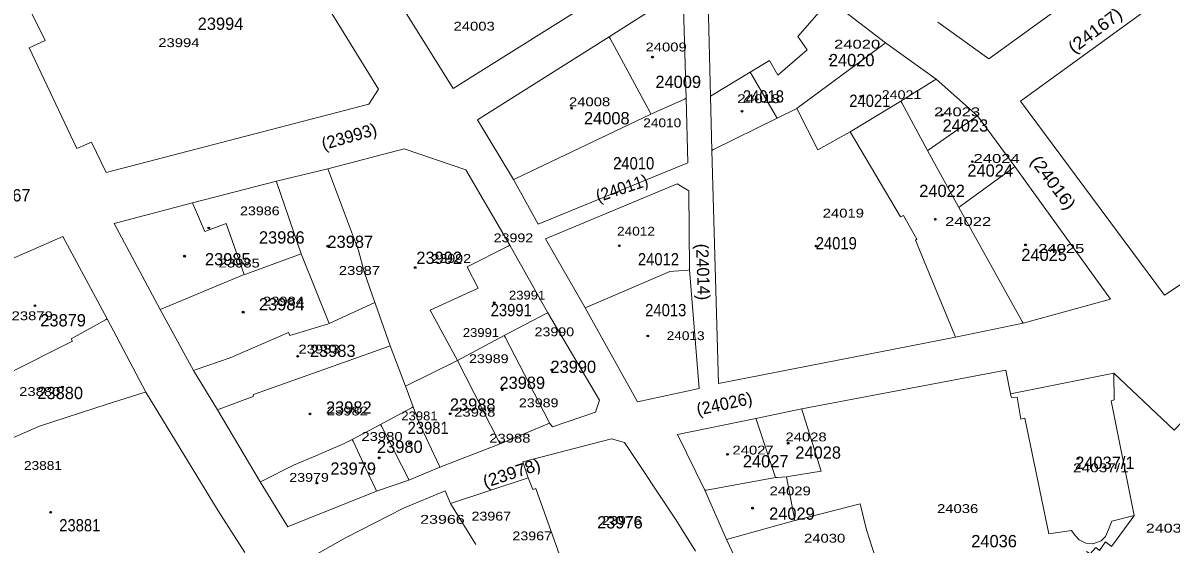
# Model space of a CAD drawing. Extents: x 649608 to 651081, y 237980 to 241202.
# Drawn here: x 650489.8 to 650826.5, y 238507.5 to 238660.5 of the extents above; entities that cross this region are included whole.
import ezdxf

# ---------------------------------------------------------------- set-up
doc = ezdxf.new("R2010")
doc.units = 0
doc.header["$PDMODE"] = 32
doc.header["$PDSIZE"] = 0.5
for name, color, linetype in [('19', 7, 'Continuous'), ('20', 7, 'Continuous'), ('6', 7, 'Continuous')]:
    doc.layers.add(name, color=color, linetype=linetype)
doc.layers.add('3', color=7, linetype='Continuous', lineweight=13)
doc.layers.add('5', color=7, linetype='Continuous', lineweight=13)

msp = doc.modelspace()

# ---------------------------------------------------------------- linework, layer by layer
at = {"layer": '3'}
for p, q in [((650640.911, 238601.421), (650633.733, 238614.499)), ((650685.081, 238611.156), (650685.298, 238587.976))]:
    msp.add_line(p, q, dxfattribs=at)
msp.add_lwpolyline([(650594.152, 238641.02), (650591.238, 238636.62), (650514.199, 238616.533), (650509.905, 238625.434), (650505.659, 238623.615), (650491.621, 238653.156), (650496.299, 238655.283), (650492.007, 238664.059), (650546.626, 238718.198)], close=True, dxfattribs=at)
for points in [[(650851.505, 238687.244), (650818.255, 238663.558), (650782.391, 238637.529), (650824.601, 238580.584), (650833.018, 238586.179), (650832.688, 238586.745), (650893.931, 238625.308)], [(650691.506, 238638.961), (650690.613, 238674.266), (650704.689, 238683.423), (650726.518, 238667.275), (650742.789, 238654.588), (650757.655, 238644.002), (650769.738, 238633.206), (650780.745, 238618.283), (650808.842, 238579.434)], [(650821.773, 238685.221), (650773.098, 238649.879), (650758.169, 238660.693)], [(650652.377, 238664), (650615.997, 238641.193), (650602.016, 238663.671), (650591.619, 238681.099)], [(650661.791, 238656.398), (650678.716, 238667.17), (650683.54, 238664.897), (650684.332, 238638.366), (650684.833, 238619.402)], [(650633.733, 238614.499), (650623.098, 238632.061), (650661.791, 238656.398)], [(650763.334, 238568.243), (650693.809, 238554.607), (650691.843, 238623.047), (650691.506, 238638.961)], [(650632.652, 238595.212), (650619.696, 238617.401), (650601.662, 238623.481), (650579.269, 238617.651), (650564.158, 238614.006), (650539.521, 238607.693)], [(650640.911, 238601.421), (650646.456, 238603.634), (650684.833, 238619.402)], [(650643.082, 238597.059), (650681.735, 238613.259), (650685.081, 238611.156)], [(650539.521, 238607.693), (650516.543, 238601.628), (650530.097, 238576.345), (650539.885, 238558.481), (650546.918, 238546.889), (650559.402, 238525.78)], [(650514.565, 238573.659), (650501.562, 238597.783), (650470.671, 238584.303), (650457.326, 238578.233), (650445.045, 238572.958), (650428.006, 238565.908), (650411.173, 238558.735)], [(650685.298, 238587.976), (650688.11, 238553.211), (650670.09, 238549.229), (650654.686, 238576.871), (650643.082, 238597.059)], [(650644.294, 238542.988), (650645.176, 238541.889), (650657.723, 238546.209), (650658.934, 238549.806), (650643.817, 238575.424), (650632.652, 238595.212)], [(650808.842, 238579.434), (650783.192, 238572.377), (650763.334, 238568.243)], [(650554.863, 238505.063), (650547.107, 238517.326), (650525.879, 238552.125), (650514.565, 238573.659)], [(650779.446, 238551.594), (650778.139, 238558.54), (650718.246, 238547.194), (650704.787, 238544.402)], [(650856.496, 238513.231), (650844.324, 238525.087), (650848.714, 238529.96), (650832.101, 238545.72), (650827.429, 238540.969), (650809.783, 238557.7), (650779.446, 238551.594)], [(650567.52, 238512.624), (650567.925, 238512.787), (650593.521, 238523.054), (650603.014, 238526.326), (650612.093, 238530.073), (650629.748, 238536.928), (650644.294, 238542.988)], [(650704.787, 238544.402), (650681.818, 238539.725), (650689.852, 238523.302), (650696.151, 238508.876)], [(650687.044, 238505.407), (650681.393, 238514.544), (650666.233, 238537.335), (650662.489, 238538.449), (650636.452, 238531.69), (650637.963, 238526.941), (650615.232, 238519.416)], [(650559.402, 238525.78), (650567.235, 238513.086), (650567.52, 238512.624)], [(650615.232, 238519.416), (650613.655, 238523.18), (650601.449, 238518.058), (650584.454, 238509.394), (650573.208, 238503.022)], [(650770.127, 238405.165), (650755.807, 238391.194), (650744.776, 238410.239), (650745.518, 238410.844), (650732.624, 238431.532), (650720.683, 238456.081), (650711.443, 238476.563), (650696.151, 238508.876)]]:
    msp.add_lwpolyline(points, dxfattribs=at)
at = {"layer": '5'}
for points in [[(650717.112, 238656.511), (650726.081, 238666.775), (650726.518, 238667.275)], [(650661.791, 238656.398), (650662.06, 238655.898), (650673.743, 238634.196), (650674.012, 238633.696)], [(650703.102, 238646.043), (650708.761, 238649.394), (650711.238, 238645.161), (650719.841, 238652.534), (650717.112, 238656.511)], [(650716.794, 238635.342), (650717.294, 238635.712), (650742.289, 238654.218), (650742.789, 238654.588)], [(650691.506, 238638.961), (650692.006, 238639.266), (650703.102, 238646.043)], [(650703.102, 238646.043), (650703.395, 238645.543), (650710.759, 238632.97), (650711.052, 238632.47)], [(650747.305, 238637.49), (650757.155, 238643.687), (650757.655, 238644.002)], [(650674.012, 238633.696), (650683.832, 238638.14), (650684.332, 238638.366)], [(650732.46, 238628.526), (650732.96, 238628.828), (650747.305, 238637.49)], [(650755.113, 238622.982), (650747.574, 238636.99), (650747.305, 238637.49)], [(650633.733, 238614.499), (650634.233, 238614.737), (650674.012, 238633.696)], [(650691.843, 238623.047), (650692.343, 238623.292), (650711.052, 238632.47), (650716.794, 238635.342)], [(650716.794, 238635.342), (650722.99, 238623.236), (650732.46, 238628.526)], [(650755.113, 238622.982), (650755.613, 238623.332), (650769.238, 238632.856), (650769.738, 238633.206)], [(650732.46, 238628.526), (650747.225, 238603.532), (650748.041, 238603.925), (650752.04, 238596.986), (650751.632, 238596.701), (650763.128, 238568.743), (650763.334, 238568.243)], [(650783.192, 238572.377), (650782.914, 238572.877), (650764.3, 238606.322), (650755.113, 238622.982)], [(650579.269, 238617.651), (650579.457, 238617.151), (650588.284, 238593.698), (650589.864, 238587.462), (650593.06, 238578.42), (650579.665, 238572.248)], [(650764.3, 238606.322), (650764.8, 238606.686), (650780.245, 238617.919), (650780.745, 238618.283)], [(650571.406, 238592.679), (650564.328, 238613.506), (650564.158, 238614.006)], [(650539.521, 238607.693), (650539.738, 238607.193), (650543.17, 238599.288), (650549.456, 238601.561), (650554.662, 238586.592)], [(650554.662, 238586.592), (650555.162, 238586.774), (650571.406, 238592.679)], [(650579.665, 238572.248), (650571.608, 238592.179), (650571.406, 238592.679)], [(650632.652, 238595.212), (650632.152, 238594.959), (650620.128, 238588.875), (650623.291, 238582.659), (650609.236, 238576.176), (650617.25, 238561.443), (650630.991, 238568.704)], [(650554.662, 238586.592), (650530.597, 238576.554), (650530.097, 238576.345)], [(650654.686, 238576.871), (650655.186, 238577.085), (650679.554, 238587.526), (650684.798, 238587.937), (650685.298, 238587.976)], [(650597.5, 238565.686), (650593.234, 238577.92), (650593.06, 238578.42)], [(650630.991, 238568.704), (650643.317, 238575.162), (650643.817, 238575.424)], [(650484.63, 238557.158), (650485.13, 238557.408), (650504.385, 238567.04), (650503.968, 238567.761), (650514.065, 238573.381), (650514.565, 238573.659)], [(650579.665, 238572.248), (650579.165, 238572.097), (650568.13, 238568.774), (650567.737, 238569.576), (650550.626, 238562.147), (650540.385, 238558.652), (650539.885, 238558.481)], [(650630.991, 238568.704), (650631.25, 238568.204), (650644.035, 238543.488), (650644.294, 238542.988)], [(650597.5, 238565.686), (650597, 238565.508), (650557.445, 238551.411), (650557.349, 238550.854), (650547.418, 238547.079), (650546.918, 238546.889)], [(650617.25, 238561.443), (650602.006, 238553.886), (650597.5, 238565.686)], [(650617.25, 238561.443), (650629.493, 238537.428), (650629.748, 238536.928)], [(650815.76, 238515.874), (650808.982, 238549.567), (650809.848, 238549.856), (650809.787, 238557.2), (650809.783, 238557.7)], [(650525.879, 238552.125), (650525.379, 238551.97), (650514.498, 238548.602), (650494.718, 238542.098), (650474.912, 238533.525), (650466.099, 238547.239), (650465.778, 238547.739)], [(650602.006, 238553.886), (650602.19, 238553.386), (650604.249, 238547.784)], [(650790.754, 238510.566), (650783.667, 238544.482), (650782.521, 238544.14), (650781.398, 238550.685), (650779.79, 238550.513), (650779.605, 238551.094), (650779.446, 238551.594)], [(650604.249, 238547.784), (650603.749, 238547.514), (650594.7, 238542.619), (650586.421, 238538.202)], [(650604.249, 238547.784), (650605.882, 238543.541), (650611.862, 238530.573), (650612.093, 238530.073)], [(650713.724, 238527.259), (650714.224, 238527.342), (650723.9, 238528.951), (650718.401, 238546.694), (650718.246, 238547.194)], [(650594.7, 238542.619), (650594.955, 238542.119), (650602.759, 238526.826), (650603.014, 238526.326)], [(650710.532, 238527.068), (650704.953, 238543.902), (650704.787, 238544.402)], [(650586.421, 238538.202), (650584.033, 238537.012), (650575.693, 238533.426), (650569.132, 238530.67), (650559.902, 238526.031), (650559.402, 238525.78)], [(650586.421, 238538.202), (650586.655, 238537.702), (650590.403, 238529.7), (650593.286, 238523.554), (650593.521, 238523.054)], [(650637.963, 238526.941), (650638.166, 238526.441), (650639.331, 238523.578), (650640.223, 238523.816), (650647.193, 238504.378), (650646.46, 238503.894), (650647.011, 238502.484)], [(650689.852, 238523.302), (650690.352, 238523.393), (650710.532, 238527.068)], [(650696.151, 238508.876), (650716.197, 238514.45), (650713.724, 238527.259)], [(650713.724, 238527.259), (650711.032, 238527.098), (650710.532, 238527.068)], [(650615.232, 238519.416), (650615.543, 238518.916), (650622.678, 238507.426)], [(650716.197, 238514.45), (650716.697, 238514.578), (650735.331, 238519.332), (650737.208, 238511.711), (650740.707, 238500.782), (650741.379, 238500.793), (650745.427, 238492.156)], [(650790.754, 238510.566), (650797.335, 238511.557), (650798.4, 238510.056), (650799.565, 238508.759), (650801.595, 238507.776), (650803.641, 238507.599), (650806.008, 238508.436), (650807.322, 238509.739), (650808.243, 238511.819), (650809.187, 238514.203), (650815.76, 238515.874)], [(650815.76, 238515.874), (650815.392, 238515.374), (650809.118, 238506.861), (650807.289, 238508.15), (650805.53, 238505.605), (650804.445, 238506.55), (650802.807, 238504.638), (650801.776, 238505.381)]]:
    msp.add_lwpolyline(points, dxfattribs=at)
at = {"layer": '6'}
for p in [(650674.487, 238650.433), (650726.577, 238649.872), (650735.591, 238638.912), (650650.776, 238635.448), (650700.718, 238634.545), (650759.437, 238633.492), (650664.936, 238619.893), (650768.27, 238619.764), (650757.437, 238602.866), (650544.348, 238600.299), (650783.882, 238595.33), (650537.234, 238592.019), (650579.224, 238594.949), (650664.73, 238595.065), (650722.496, 238594.974), (650604.89, 238588.683), (650493.348, 238577.47), (650554.417, 238575.58), (650628.039, 238578.327), (650673.08, 238568.602), (650570.393, 238562.654), (650644.95, 238558.656), (650501.452, 238553.592), (650630.429, 238552.816), (650574.029, 238545.733), (650615.138, 238545.758), (650603.206, 238537.055), (650714.281, 238537.131), (650594.313, 238532.836), (650696.487, 238533.852), (650799.262, 238532.649), (650576.021, 238525.413), (650703.818, 238518.067), (650497.97, 238516.876), (650662.052, 238515.362)]:
    msp.add_point(p, dxfattribs=at)

# ---------------------------------------------------------------- texts
at = {"layer": '19'}
for s, rotation, width, p in [('(24167)', 37.028, 1.1, (650798.048, 238651.337)), ('(24016)', 306.845, 1.1, (650785.071, 238619.858)), ('(24011)', 18.398, 0.95, (650658.569, 238607.802)), ('(23978)', 18.317, 1.05, (650625.428, 238523.944))]:
    msp.add_text(s, height=3.6, rotation=rotation, dxfattribs=dict(at, width=width)).set_placement(p)
for s, p in [('23994', (650541.083, 238658.432)), ('24020', (650726.195, 238647.767)), ('24009', (650675.32, 238641.367)), ('24008', (650654.373, 238630.702)), ('24023', (650759.541, 238628.569)), ('24024', (650766.809, 238615.344)), ('24022', (650752.701, 238609.372)), ('23867', (650478.667, 238608.091)), ('23986', (650559.038, 238595.72)), ('23987', (650579.131, 238594.44)), ('23985', (650543.22, 238589.321)), ('23992', (650605.209, 238589.747)), ('24025', (650782.627, 238590.601)), ('23984', (650559.037, 238576.096)), ('23879', (650494.912, 238571.403)), ('23983', (650574.001, 238562.444)), ('23990', (650644.54, 238557.751)), ('23989', (650629.578, 238553.059)), ('23880', (650494.056, 238550.072)), ('23982', (650578.704, 238545.806)), ('23988', (650615.042, 238546.66)), ('23980', (650593.666, 238534.288)), ('24028', (650716.361, 238532.583)), ('24027', (650700.971, 238530.023)), ('24037/1', (650798.444, 238529.596)), ('23979', (650579.985, 238527.889)), ('24029', (650708.666, 238514.665)), ('23976', (650658.22, 238512.105)), ('24036', (650767.957, 238506.6))]:
    msp.add_text(s, height=3.6, dxfattribs=at).set_placement(p)
at = {"layer": '19', "width": 0.9}
for s, p in [('24018', (650700.971, 238637.101)), ('24021', (650732.18, 238635.821)), ('24010', (650662.923, 238617.477)), ('24019', (650722.347, 238594.014)), ('24012', (650670.19, 238589.321)), ('23991', (650627.013, 238574.389)), ('24013', (650672.328, 238574.389)), ('23981', (650602.644, 238539.834)), ('23881', (650500.47, 238511.251))]:
    msp.add_text(s, height=3.6, dxfattribs=at).set_placement(p)
at = {"layer": '19'}
for s, rotation, p in [('(23993)', 16.023, (650578.008, 238623.119)), ('(24014)', 271.851, (650687.241, 238595.628)), ('(24026)', 11.984, (650687.781, 238545.243))]:
    msp.add_text(s, height=3.6, rotation=rotation, dxfattribs=at).set_placement(p)
at = {"layer": '20'}
for s, width, p in [('24003', 1.25, (650616.117, 238658.202)), ('23994', 1.25, (650529.517, 238653.369)), ('24009', 1.25, (650672.414, 238652.098)), ('24020 ', 1.4, (650727.713, 238652.916)), ('24018 ', 1.3, (650699.277, 238636.927)), ('24021 ', 1.2, (650741.704, 238638.104)), ('24008', 1.25, (650649.975, 238636.018)), ('24023 ', 1.4, (650757.04, 238633.063)), ('24010', 1.15, (650671.767, 238629.848)), ('24024 ', 1.4, (650768.635, 238619.384)), ('23986', 1.2, (650553.499, 238604.019)), ('24019 ', 1.25, (650724.397, 238603.352)), ('24022 ', 1.4, (650760.278, 238600.913)), ('24012', 1.15, (650664.063, 238598.043)), ('23992', 1.2, (650627.875, 238596.104)), ('24025 ', 1.4, (650787.581, 238592.984)), ('23992', 1.2, (650609.654, 238590.048)), ('23985', 1.25, (650547.214, 238588.695)), ('23987', 1.25, (650582.465, 238586.52)), ('23984', 1.25, (650560.188, 238577.534)), ('23991', 1.1, (650632.373, 238579.277)), ('23879', 1.25, (650486.505, 238573.23)), ('23991', 1.1, (650618.839, 238568.292)), ('23990', 1.2, (650639.877, 238568.526)), ('24013', 1.15, (650678.631, 238567.379)), ('23983', 1.25, (650570.633, 238563.44)), ('23989', 1.2, (650620.653, 238560.63)), ('23880', 1.25, (650488.712, 238550.975)), ('23989', 1.2, (650635.286, 238547.678)), ('23982', 1.25, (650578.937, 238545.272)), ('23981', 1.1, (650600.798, 238543.853)), ('23988', 1.25, (650616.302, 238544.928)), ('23980', 1.25, (650589.095, 238537.799)), ('23988', 1.25, (650626.591, 238537.301)), ('24028', 1.25, (650713.461, 238537.67)), ('24027', 1.25, (650697.922, 238533.819)), ('23881', 1.15, (650490.138, 238529.294)), ('23979', 1.2, (650567.943, 238525.786)), ('24037/1', 1.3, (650797.792, 238528.617)), ('24029', 1.25, (650708.803, 238521.82)), ('24036', 1.25, (650757.924, 238516.638)), ('23966 ', 1.35, (650606.331, 238513.478)), ('23967', 1.2, (650621.389, 238514.424)), ('23976', 1.2, (650659.684, 238513.142)), ('24037/2', 1.35, (650819.179, 238510.887)), ('23967', 1.2, (650633.386, 238508.627)), ('24030', 1.25, (650718.913, 238507.94))]:
    msp.add_text(s, height=2.6, dxfattribs=dict(at, width=width)).set_placement(p)

doc.saveas('drawing.dxf')
